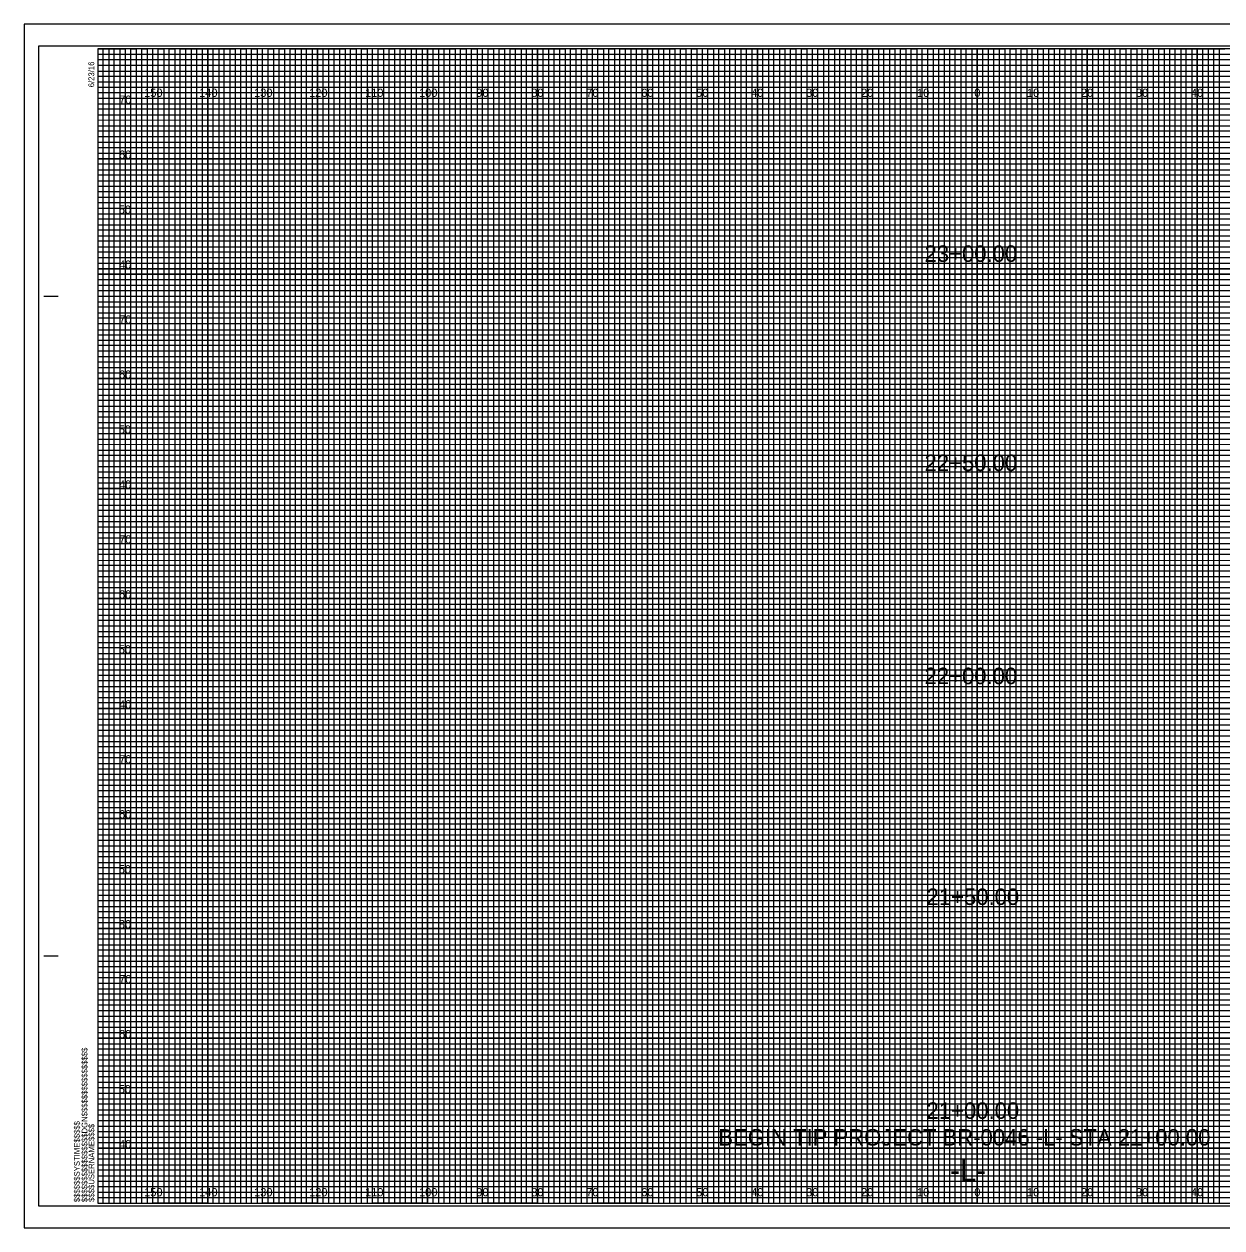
# Model space of a CAD drawing. Extents: x -13 to 323, y 435 to 654.
# Drawn here: x -13.4 to 204.5, y 435.5 to 654.5 of the extents above; entities that cross this region are included whole.
import ezdxf

# ---------------------------------------------------------------- set-up
doc = ezdxf.new("R2010")
doc.units = 0
for name, color, linetype in [('Prop XS Alignment Label', 7, 'Continuous'), ('Prop XS Elevation Labels', 7, 'Continuous'), ('Prop XS Offset Labels', 7, 'Continuous'), ('Prop XS Station Labels', 7, 'Continuous'), ('Sheet Cross Section CELL', 7, 'Continuous'), ('Sheet Cross Section Grid Major CELL', 7, 'Continuous'), ('Sheet Cross Section Grid Middle CELL', 7, 'Continuous'), ('Sheet Cross Section Grid Minor 1 CELL', 7, 'Continuous'), ('Sheet Cross Section Grid Minor 2 CELL', 7, 'Continuous'), ('Sheet Cutting Line CELL', 7, 'Continuous'), ('Sheet DOT Grid CELL', 7, 'Continuous'), ('Sheet Plot Border Inside CELL', 7, 'Continuous'), ('Sheet Plot Border Outside CELL', 7, 'Continuous')]:
    doc.layers.add(name, color=color, linetype=linetype)

msp = doc.modelspace()

# ---------------------------------------------------------------- linework, layer by layer
at = {"layer": 'Sheet Cross Section CELL'}
for p, q in [((-9.8, 605), (-7.3, 605)), ((-9.7, 605), (-7.2, 605)), ((-9.8, 485), (-7.3, 485)), ((-9.7, 485), (-7.2, 485)), ((0, 440), (0, 440)), ((0, 440), (0, 440)), ((0, 440), (0, 440)), ((0, 440), (0, 440)), ((0, 440), (0, 440)), ((0, 440), (0, 440)), ((0, 440), (0, 440))]:
    msp.add_line(p, q, dxfattribs=at)
msp.add_lwpolyline([(320, 650), (0, 650), (0, 440), (320, 440)], close=True, dxfattribs=at)
at = {"layer": 'Sheet Cross Section Grid Major CELL'}
for p, q in [((10, 650), (0, 650)), ((10, 440), (10, 650)), ((30, 650), (20, 650)), ((20, 650), (20, 440)), ((30, 440), (30, 650)), ((50, 650), (40, 650)), ((40, 650), (40, 440)), ((50, 440), (50, 650)), ((70, 650), (60, 650)), ((60, 650), (60, 440)), ((70, 440), (70, 650)), ((90, 650), (80, 650)), ((80, 650), (80, 440)), ((90, 440), (90, 650)), ((110, 650), (100, 650)), ((100, 650), (100, 440)), ((110, 440), (110, 650)), ((130, 650), (120, 650)), ((120, 650), (120, 440)), ((130, 440), (130, 650)), ((150, 650), (140, 650)), ((140, 650), (140, 440)), ((150, 440), (150, 650)), ((170, 650), (160, 650)), ((160, 650), (160, 440)), ((170, 440), (170, 650)), ((190, 650), (180, 650)), ((180, 650), (180, 440)), ((190, 440), (190, 650)), ((210, 650), (200, 650)), ((200, 650), (200, 440)), ((20, 440), (10, 440)), ((40, 440), (30, 440)), ((60, 440), (50, 440)), ((80, 440), (70, 440)), ((100, 440), (90, 440)), ((120, 440), (110, 440)), ((140, 440), (130, 440)), ((160, 440), (150, 440)), ((180, 440), (170, 440)), ((200, 440), (190, 440))]:
    msp.add_line(p, q, dxfattribs=at)
for points in [[(0, 640), (320, 640), (320, 630), (0, 630)], [(0, 620), (320, 620), (320, 610), (0, 610)], [(0, 600), (320, 600), (320, 590), (0, 590)], [(0, 580), (320, 580), (320, 570), (0, 570)], [(0, 560), (320, 560), (320, 550), (0, 550)], [(0, 540), (320, 540), (320, 530), (0, 530)], [(0, 520), (320, 520), (320, 510), (0, 510)], [(0, 500), (320, 500), (320, 490), (0, 490)], [(0, 480), (320, 480), (320, 470), (0, 470)], [(0, 460), (320, 460), (320, 450), (0, 450)]]:
    msp.add_lwpolyline(points, dxfattribs=at)
at = {"layer": 'Sheet Cross Section Grid Middle CELL'}
for points in [[(0, 650), (5, 650), (5, 440), (15, 440), (15, 650), (25, 650), (25, 440), (35, 440), (35, 650), (45, 650), (45, 440), (55, 440), (55, 650), (65, 650), (65, 440), (75, 440), (75, 650), (85, 650), (85, 440), (95, 440), (95, 650), (105, 650), (105, 440), (115, 440), (115, 650), (125, 650), (125, 440), (135, 440), (135, 650), (145, 650), (145, 440), (155, 440), (155, 650), (165, 650), (165, 440), (175, 440), (175, 650), (185, 650), (185, 440), (195, 440), (195, 650), (205, 650)], [(0, 645), (275, 645)], [(0, 625), (320, 625), (320, 635), (0, 635)], [(0, 605), (320, 605), (320, 615), (0, 615)], [(0, 585), (320, 585), (320, 595), (0, 595)], [(0, 565), (320, 565), (320, 575), (0, 575)], [(0, 545), (320, 545), (320, 555), (0, 555)], [(0, 525), (320, 525), (320, 535), (0, 535)], [(0, 505), (320, 505), (320, 515), (0, 515)], [(0, 485), (320, 485), (320, 495), (0, 495)], [(0, 465), (320, 465), (320, 475), (0, 475)], [(0, 445), (320, 445), (320, 455), (0, 455)]]:
    msp.add_lwpolyline(points, dxfattribs=at)
at = {"layer": 'Sheet Cross Section Grid Minor 1 CELL'}
for p, q in [((0, 649), (260, 649)), ((260, 647.98), (0, 647.98)), ((0, 647.98), (0, 647)), ((0, 647), (260, 647)), ((260, 645.89), (0, 645.89)), ((0, 645.89), (0, 644)), ((0, 644), (320, 644))]:
    msp.add_line(p, q, dxfattribs=at)
for points in [[(0, 643), (270, 643), (320, 643), (320, 642), (0, 642)], [(0, 641), (320, 641), (320, 639), (0, 639)], [(0, 638), (320, 638), (320, 637), (0, 636.98)], [(0, 636), (320, 636), (320, 634), (0, 634)], [(0, 633), (320, 633), (320, 632), (0, 632)], [(0, 631), (320, 631), (320, 629), (0, 629)], [(0, 628), (320, 628), (320, 627), (0, 627)], [(0, 626), (320, 626), (320, 624), (0, 624)], [(0, 623), (320, 623), (320, 622), (0, 622)], [(0, 621), (320, 621), (320, 619), (0, 619)], [(0, 618), (320, 618), (320, 617), (0, 617)], [(0, 616), (320, 616), (320, 613.95), (320, 613), (320, 612), (0, 612)], [(0, 614), (320, 614), (320, 613), (0, 613)], [(0, 611), (320, 611), (320, 609), (0, 609.03)], [(0, 609.03), (320, 609), (320, 608), (0, 608)], [(0, 607), (320, 607), (320, 606), (0, 606)], [(0, 604), (320, 604), (320, 603), (0, 603)], [(0, 602), (320, 602), (320, 601), (0, 601)], [(-0.07, 598.89), (320, 598.89), (320, 597.88), (-0.07, 597.88)], [(0, 597), (320, 597), (320, 596), (0, 596)], [(0, 594), (320, 594), (320, 593), (0, 593)], [(0, 592), (320, 592), (320, 591), (0, 591)], [(0, 589), (320, 589), (320, 588), (0, 588)], [(0, 587), (320, 587), (320, 586), (0, 586)], [(0, 584), (320, 584), (320, 583), (0, 583)], [(0, 582), (320, 582), (320, 581), (0, 581)], [(0, 579), (320, 579), (319.99, 577.98), (0, 578)], [(0, 577), (320, 577), (320, 576), (0, 576)], [(0, 574), (320, 574), (320, 573), (0, 573)], [(0, 572), (320, 572), (320, 571), (0, 571)], [(0, 569), (320, 569), (320, 568), (0, 568)], [(0, 567), (320, 567), (320, 566), (0, 566)], [(0, 564), (320, 564), (320, 563), (0, 563)], [(0, 562), (320, 562), (320, 561), (0, 561)], [(0, 559), (320, 559), (320, 558), (0, 558)], [(0, 556.99), (320.07, 556.91), (320, 556), (0, 556)], [(0, 554), (320, 554), (320, 553), (0, 553)], [(0, 552), (320, 552), (320, 551), (0, 551)], [(0, 549), (320, 549), (320, 548), (0, 548)], [(0, 547), (320, 547), (320, 546), (0, 546)], [(0, 544), (320, 544), (320, 543), (0, 543)], [(0, 542), (320, 542), (320, 541), (0, 541)], [(0, 539), (320, 539), (320, 538), (0, 538)], [(0, 537), (320, 537), (320, 536), (0, 536)], [(0, 534), (320, 534), (320, 533), (0, 533)], [(0, 532), (320, 532), (320, 531), (0, 531)], [(0, 529), (320, 529), (320, 528), (0, 528)], [(0, 527), (320, 527), (320, 526), (0, 526)], [(0, 524), (320, 524), (320, 523), (0, 523)], [(0, 522), (320, 522), (320, 521), (0, 521)], [(0, 519), (320, 519), (319.99, 517.98), (0, 518)], [(0, 517), (320, 517), (320, 516), (0, 516)], [(0, 514), (320, 514), (320, 513), (0, 513)], [(0, 512), (320, 512), (320, 511), (0, 511)], [(0, 509), (320, 509), (320, 508), (0, 508)], [(0, 507), (320, 507), (320, 506), (0, 506)], [(0, 504), (320, 504), (320, 503), (0, 503)], [(0, 502), (320, 502), (320, 501), (0, 501)], [(0, 499), (320, 499), (320, 498), (0, 498)], [(0, 496.99), (320.07, 496.91), (320, 496), (0, 496)], [(0, 494), (320, 494), (320, 493), (0, 493)], [(0, 492), (320, 492), (320, 491), (0, 491)], [(0, 489), (320, 489), (320, 488), (0, 488)], [(0, 487), (320, 487), (320, 486), (0, 486)], [(0, 484), (320, 484), (320, 483), (0, 483)], [(0, 482), (320, 482), (320, 481), (0, 481)], [(0, 479), (320, 479), (320, 478), (0, 478)], [(0, 477), (320, 477), (320, 476), (0, 476)], [(0, 474), (320, 474), (320, 473), (0, 473)], [(0, 472), (320, 472), (320, 471), (0, 471)], [(0, 469), (320, 469), (320, 468), (0, 468)], [(0, 467), (320, 467), (320, 466), (0, 466)], [(0, 464), (320, 464), (320, 463), (0, 463)], [(0, 462), (320, 462), (320, 461), (0, 461)], [(0, 459), (320, 459), (320, 458), (0, 458)], [(0, 457), (320, 457), (320, 456), (0, 456)], [(0, 454), (320, 454), (320, 453), (0, 453)], [(0, 452), (320, 452), (320, 451), (0, 451)], [(0, 449), (320, 449), (320, 448), (0, 448)], [(0, 447), (320, 447), (320, 446), (0, 446)], [(0, 444), (320, 444), (320, 443), (0, 443)], [(0, 442), (320, 442), (320, 441), (0, 441)]]:
    msp.add_lwpolyline(points, dxfattribs=at)
at = {"layer": 'Sheet Cross Section Grid Minor 2 CELL'}
for points in [[(0, 440), (1, 440), (1, 650), (2, 650), (2, 440)], [(2, 440), (3, 440), (3, 650), (4, 650), (4, 440)], [(5, 440), (6, 440), (6, 650), (7, 650), (7, 440)], [(7, 440), (8, 440), (8, 650), (9, 650), (9, 440)], [(10, 440), (11, 440), (11, 650), (12, 650), (12, 440)], [(12, 440), (13, 440), (13, 650), (14, 650), (14, 440)], [(15, 440), (16, 440), (16, 650), (17, 650), (17, 440)], [(17, 440), (18, 440), (18, 650), (19, 650), (19, 440)], [(20, 440), (21, 440), (21, 650), (22, 650), (22, 440)], [(22, 440), (23, 440), (23, 650), (24, 650), (24, 440)], [(25, 440), (26, 440), (26, 650), (27, 650), (27, 440)], [(27, 440), (28, 440), (28, 650), (29, 650), (29, 440)], [(30, 440), (31, 440), (31, 650), (32, 650), (32, 440)], [(32, 440), (33, 440), (33, 650), (34, 650), (34, 440)], [(35, 440), (36, 440), (36, 650), (37, 650), (37, 440)], [(37, 440), (38, 440), (38, 650), (39, 650), (39, 440)], [(40, 440), (41, 440), (41, 650), (42, 650), (42, 440)], [(42, 440), (43, 440), (43, 650), (44, 650), (44, 440)], [(45, 440), (46, 440), (46, 650), (47, 650), (47, 440)], [(47, 440), (48, 440), (48, 650), (49, 650), (49, 440)], [(50, 440), (51, 440), (51, 650), (52, 650), (52, 440)], [(52, 440), (53, 440), (53, 650), (54, 650), (54, 440)], [(55, 440), (56, 440), (56, 650), (57, 650), (57, 440)], [(57, 440), (58, 440), (58, 650), (59, 650), (59, 440)], [(60, 440), (61, 440), (61, 650), (62, 650), (62, 440)], [(62, 440), (63, 440), (63, 650), (64, 650), (64, 440)], [(65, 440), (66, 440), (66, 650), (67, 650), (67, 440)], [(67, 440), (68, 440), (68, 650), (69, 650), (69, 440)], [(70, 440), (71, 440), (71, 650), (72, 650), (72, 440)], [(72, 440), (73, 440), (73, 650), (74, 650), (74, 440)], [(75, 440), (76, 440), (76, 650), (77, 650), (77, 440)], [(77, 440), (78, 440), (78, 650), (79, 650), (79, 440)], [(80, 440), (81, 440), (81, 650), (82, 650), (82, 440)], [(82, 440), (83, 440), (83, 650), (84, 650), (84, 440)], [(85, 440), (86, 440), (86, 650), (87, 650), (87, 440)], [(87, 440), (88, 440), (88, 650), (89, 650), (89, 440)], [(90, 440), (91, 440), (91, 650), (92, 650), (92, 440)], [(92, 440), (93, 440), (93, 650), (94, 650), (94, 440)], [(95, 440), (96, 440), (96, 650), (97, 650), (97, 440)], [(97, 440), (98, 440), (98, 650), (99, 650), (99, 440)], [(100, 440), (101, 440), (101, 650), (102, 650), (102, 440)], [(102, 440), (103, 440), (103, 650), (104, 650), (104, 440)], [(105, 440), (106, 440), (106, 650), (107, 650), (107, 440)], [(107, 440), (108, 440), (108, 650), (109, 650), (109, 440)], [(110, 440), (111, 440), (111, 650), (112, 650), (112, 440)], [(112, 440), (113, 440), (113, 650), (114, 650), (114, 440)], [(115, 440), (116, 440), (116, 650), (117, 650), (117, 440)], [(117, 440), (118, 440), (118, 650), (119, 650), (119, 440)], [(120, 440), (121, 440), (121, 650), (122, 650), (122, 440)], [(122, 440), (123, 440), (123, 650), (124, 650), (124, 440)], [(125, 440), (126, 440), (126, 650), (127, 650), (127, 440)], [(127, 440), (128, 440), (128, 650), (129, 650), (129, 440)], [(130, 440), (131, 440), (131, 650), (132, 650), (132, 440)], [(132, 440), (133, 440), (133, 650), (134, 650), (134, 440)], [(135, 440), (136, 440), (136, 650), (137, 650), (137, 440)], [(137, 440), (138, 440), (138, 650), (139, 650), (139, 440)], [(140, 440), (141, 440), (141, 650), (142, 650), (142, 440)], [(142, 440), (143, 440), (143, 650), (144, 650), (144, 440)], [(145, 440), (146, 440), (146, 650), (147, 650), (147, 440)], [(147, 440), (148, 440), (148, 650), (149, 650), (149, 440)], [(150, 440), (151, 440), (151, 650), (152, 650), (152, 440)], [(152, 440), (153, 440), (153, 650), (154, 650), (154, 440)], [(155, 440), (156, 440), (156, 650), (157, 650), (157, 440)], [(157, 440), (158, 440), (158, 650), (159, 650), (159, 440)], [(160, 440), (161, 440), (161, 650), (162, 650), (162, 440)], [(162, 440), (163, 440), (163, 650), (164, 650), (164, 440)], [(165, 440), (166, 440), (166, 650), (167, 650), (167, 440)], [(167, 440), (168, 440), (168, 650), (169, 650), (169, 440)], [(170, 440), (171, 440), (171, 650), (172, 650), (172, 440)], [(172, 440), (173, 440), (173, 650), (174, 650), (174, 440)], [(175, 440), (176, 440), (176, 650), (177, 650), (177, 440)], [(177, 440), (178, 440), (178, 650), (179, 650), (179, 440)], [(180, 440), (181, 440), (181, 650), (182, 650), (182, 440)], [(182, 440), (183, 440), (183, 650), (184, 650), (184, 440)], [(185, 440), (186, 440), (186, 650), (187, 650), (187, 440)], [(187, 440), (188, 440), (188, 650), (189, 650), (189, 440)], [(190, 440), (191, 440), (191, 650), (192, 650), (192, 440)], [(192, 440), (193, 440), (193, 650), (194, 650), (194, 440)], [(195, 440), (196, 440), (196, 650), (197, 650), (197, 440)], [(197, 440), (198, 440), (198, 650), (199, 650), (199, 440)], [(200, 440), (201, 440), (201, 650), (202, 650), (202, 440)], [(202, 440), (203, 440), (203, 650), (204, 650), (204, 440)]]:
    msp.add_lwpolyline(points, dxfattribs=at)
at = {"layer": 'Sheet Cutting Line CELL'}
for p, q in [((323.3, 654.5), (-13.4, 654.5)), ((-13.4, 654.5), (-13.4, 435.5)), ((-13.4, 435.5), (323.3, 435.5))]:
    msp.add_line(p, q, dxfattribs=at)
at = {"layer": 'Sheet DOT Grid CELL'}
for p, q in [((10, 440), (10, 650)), ((20, 440), (20, 650)), ((30, 440), (30, 650)), ((40, 440), (40, 650)), ((50, 440), (50, 650)), ((60, 440), (60, 650)), ((70, 440), (70, 650)), ((80, 440), (80, 650)), ((90, 440), (90, 650)), ((100, 440), (100, 650)), ((110, 440), (110, 650)), ((120, 440), (120, 650)), ((130, 440), (130, 650)), ((140, 440), (140, 650)), ((150, 440), (150, 650)), ((160, 440), (160, 650)), ((170, 440), (170, 650)), ((180, 440), (180, 650)), ((190, 440), (190, 650)), ((200, 440), (200, 650)), ((0, 640), (320, 640)), ((0, 630), (320, 630)), ((0, 620), (320, 620)), ((0, 610), (320, 610)), ((0, 600), (320, 600)), ((0, 590), (320, 590)), ((0, 580), (320, 580)), ((0, 570), (320, 570)), ((0, 560), (320, 560)), ((0, 550), (320, 550)), ((0, 540), (320, 540)), ((0, 530), (320, 530)), ((0, 520), (320, 520)), ((0, 510), (320, 510)), ((0, 500), (320, 500)), ((0, 490), (320, 490)), ((0, 480), (320, 480)), ((0, 470), (320, 470)), ((0, 460), (320, 460)), ((0, 450), (320, 450))]:
    msp.add_line(p, q, dxfattribs=at)
at = {"layer": 'Sheet Plot Border Inside CELL'}
msp.add_lwpolyline([(-10.8, 439.5), (322.4, 439.5), (322.4, 650.5), (-10.8, 650.5)], close=True, dxfattribs=at)
at = {"layer": 'Sheet Plot Border Outside CELL'}
msp.add_lwpolyline([(-13.4, 435.5), (323.3, 435.5), (323.3, 654.5), (-13.4, 654.5)], close=True, dxfattribs=at)

# ---------------------------------------------------------------- texts
at = {"layer": 'Prop XS Alignment Label'}
msp.add_text('-L-', height=4, dxfattribs=at).set_placement((155.06, 444))
at = {"layer": 'Prop XS Elevation Labels'}
for s, p in [('70', (3.9, 640)), ('60', (3.87, 630)), ('50', (3.82, 620)), ('40', (3.87, 610)), ('70', (3.9, 600)), ('60', (3.87, 590)), ('50', (3.82, 580)), ('40', (3.87, 570)), ('70', (3.9, 560)), ('60', (3.87, 550)), ('50', (3.82, 540)), ('40', (3.87, 530)), ('70', (3.9, 520)), ('60', (3.87, 510)), ('50', (3.82, 500)), ('80', (3.84, 490)), ('70', (3.9, 480)), ('60', (3.87, 470)), ('50', (3.82, 460)), ('40', (3.87, 450))]:
    msp.add_text(s, height=1.5, dxfattribs=at).set_placement(p)
at = {"layer": 'Prop XS Offset Labels'}
for s, p in [('150', (8.44, 641.25)), ('140', (18.44, 641.25)), ('130', (28.44, 641.25)), ('120', (38.44, 641.25)), ('110', (48.62, 641.25)), ('100', (58.44, 641.25)), ('90', (68.86, 641.25)), ('80', (78.86, 641.25)), ('70', (88.86, 641.25)), ('60', (98.86, 641.25)), ('50', (108.86, 641.25)), ('40', (118.86, 641.25)), ('30', (128.86, 641.25)), ('20', (138.86, 641.25)), ('10', (149.04, 641.25)), ('0', (159.45, 641.25)), ('0', (159.45, 641.25)), ('10', (169.04, 641.25)), ('20', (178.86, 641.25)), ('30', (188.86, 641.25)), ('40', (198.86, 641.25)), ('150', (8.44, 441.25)), ('140', (18.44, 441.25)), ('130', (28.44, 441.25)), ('120', (38.44, 441.25)), ('110', (48.62, 441.25)), ('100', (58.44, 441.25)), ('90', (68.86, 441.25)), ('80', (78.86, 441.25)), ('70', (88.86, 441.25)), ('60', (98.86, 441.25)), ('50', (108.86, 441.25)), ('40', (118.86, 441.25)), ('30', (128.86, 441.25)), ('20', (138.86, 441.25)), ('10', (149.04, 441.25)), ('0', (159.45, 441.25)), ('0', (159.45, 441.25)), ('10', (169.04, 441.25)), ('20', (178.86, 441.25)), ('30', (188.86, 441.25)), ('40', (198.86, 441.25))]:
    msp.add_text(s, height=1.5, dxfattribs=at).set_placement(p)
at = {"layer": 'Prop XS Station Labels'}
for s, p in [('23+00.00', (150.41, 611.24)), ('22+50.00', (150.41, 573.19)), ('22+00.00', (150.41, 534.42)), ('21+50.00', (150.77, 494.25)), ('21+00.00', (150.77, 455.34)), ('BEGIN TIP PROJECT BR-0046 -L- STA 21+00.00', (112.89, 450.48))]:
    msp.add_text(s, height=3, dxfattribs=at).set_placement(p)
at = {"layer": 'Sheet Cross Section CELL'}
for s, p in [('6/23/16', (-0.65, 643)), ('$$$$$$$$$$$$$$$$DGN$$$$$$$$$$$$$$$$', (-1.88, 440.18)), ('$$$$$$SYSTIME$$$$$', (-3.26, 440.18)), ('$$$$USERNAME$$$$', (-0.62, 440.23))]:
    msp.add_text(s, height=1.05, rotation=90, dxfattribs=at).set_placement(p)

doc.saveas('drawing.dxf')
